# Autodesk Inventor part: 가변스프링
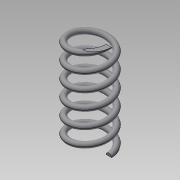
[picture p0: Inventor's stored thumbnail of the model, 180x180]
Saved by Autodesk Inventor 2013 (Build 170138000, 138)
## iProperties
Created: 2020-02
Part Number: 가변스프링
Material: 일반
Document SubType Name: Modeling
Designer: Administrator
Density: 1 g/cm^3
Author: Administrator
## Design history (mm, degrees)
sketch "스케치1"
  geometry: L1 (0, 0)-(7, 0); L2 (7, 0)-(7, 35.5); L3 (7, 35.5)-(0, 35.5); L4 (0, 35.5)-(0, 0); C1 r 1 at (7, 0)
  constraints: 8 end point, 2 parallel, 1 centre point, 1 coincident, 1 horizontal, 1 perpendicular
  dimensions: "d0" = 2 diameter of C1; "d2" = 14 diameter of L2 L4; "d3" = 35.5 distance of L1.end L2.end (derived)
feature "코일1" sketch "스케치1" pitch "d4" = 10; turns "d6" = 6; dims "d5" = 35.5 (= d3), "d7" = 0, angle "d8" = 90 deg, angle "d9" = 90 deg, "d10" = 0, "d11" = 0
sketch "스케치2"
  geometry: L1 (35.5, -8.5)-(0, -8.5); L2 (0, -8.5)-(0, 8.5); L3 (0, 8.5)-(35.5, 8.5); L4 (35.5, 8.5)-(35.5, -8.5); 2 further points
  constraints: 8 end point, 2 parallel, 1 coincident, 1 horizontal, 1 midpoint, 1 perpendicular
  dimensions: "d12" = 17 distance of L3.end L1.start; "d14" = 35.5 distance of L2.end L3.end (derived)
extrude "돌출1" sketch "스케치2" stored distance "d15" = 17; taper "d16" = 0 deg
node "솔리드1"
